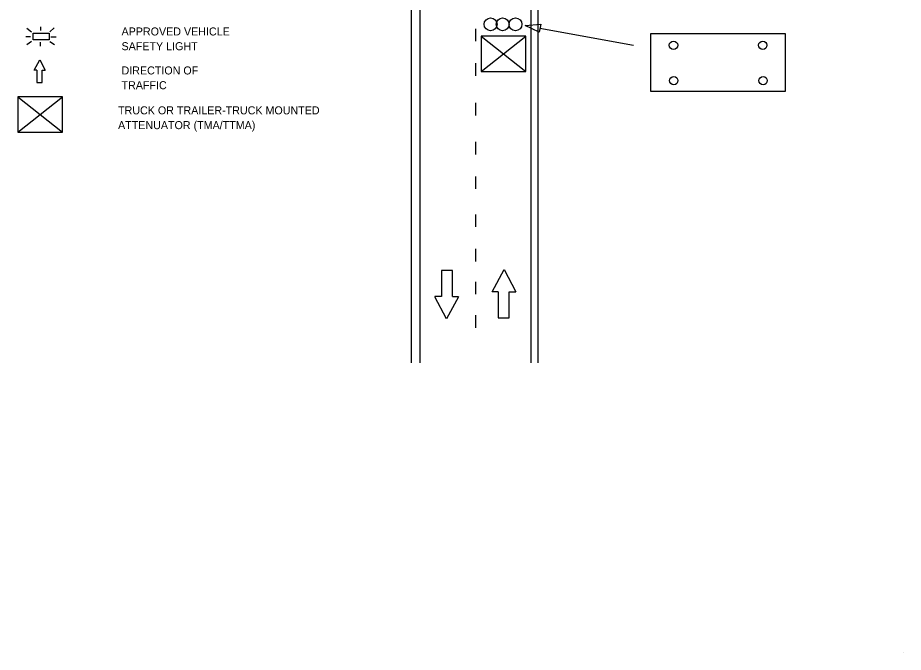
# Model space of a CAD drawing. Extents: x 1531.94 to 1538.58, y 1529.59 to 1539.32.
# Drawn here: x 1531.94 to 1538.58, y 1529.59 to 1534.35 of the extents above; entities that cross this region are included whole.
import ezdxf

# ---------------------------------------------------------------- set-up
doc = ezdxf.new("R2010")
doc.units = 0
for name, color, linetype in [('DETL-DIMS', 7, 'Continuous'), ('DETL-LINE', 7, 'Continuous'), ('DETL-NOTE', 7, 'Continuous'), ('TTLB-TEXT', 7, 'Continuous'), ('USER-BORD', 7, 'Continuous')]:
    doc.layers.add(name, color=color, linetype=linetype)

# ---------------------------------------------------------------- blocks, each defined once
blk = doc.blocks.new('BAR')
at = {"layer": 'USER-BORD'}
for p, q in [((-0.011, 0.0696), (-0.0512, 0.1025)), ((0.0695, 0.1172), (0.0695, 0.0842)), ((0.15, 0.0732), (0.1866, 0.1062)), ((-0.0183, 0.0293), (-0.0585, 0.0293)), ((0.0037, 0.0037), (0.0037, 0.0622)), ((0.0037, 0.0622), (0.1427, 0.0622)), ((0.1427, 0.0037), (0.0037, 0.0037)), ((0.1427, 0.0622), (0.1427, 0.0037)), ((0.1573, 0.0293), (0.2049, 0.0293)), ((-0.011, -0.011), (-0.0512, -0.0403)), ((0.0658, -0.0183), (0.0658, -0.0513)), ((0.15, -0.011), (0.1902, -0.0366))]:
    blk.add_line(p, q, dxfattribs=at)

msp = doc.modelspace()

# ---------------------------------------------------------------- linework, layer by layer
at = {"layer": 'DETL-DIMS'}
msp.add_line((1535.8604, 1534.2712), (1536.5606, 1534.1437), dxfattribs=at)
msp.add_lwpolyline([(1535.7487, 1534.2927), (1535.866, 1534.3021), (1535.8552, 1534.2427)], close=True, dxfattribs=at)
at = {"layer": 'DETL-LINE'}
for p, q in [((1535.7908, 1538.5962), (1535.7908, 1531.7633)), ((1535.8438, 1538.5962), (1535.8438, 1531.7633)), ((1534.8945, 1538.2527), (1534.8945, 1531.7633)), ((1534.9605, 1538.2527), (1534.9605, 1531.7633)), ((1535.3789, 1534.1741), (1535.3789, 1534.2675)), ((1535.754, 1534.2115), (1535.4183, 1534.2115)), ((1535.4183, 1534.2115), (1535.4183, 1533.9471)), ((1535.4183, 1533.9471), (1535.754, 1534.2115)), ((1535.4183, 1534.2115), (1535.754, 1533.9471)), ((1535.754, 1533.9471), (1535.754, 1534.2115)), ((1537.701, 1534.2291), (1536.6891, 1534.2291)), ((1536.6891, 1534.2291), (1536.6891, 1533.7988)), ((1536.8577, 1534.2291), (1536.8577, 1534.2291)), ((1537.0264, 1534.2291), (1537.0264, 1534.2291)), ((1537.195, 1534.2291), (1537.195, 1534.2291)), ((1537.3638, 1534.2291), (1537.3638, 1534.2291)), ((1537.5324, 1534.2291), (1537.5324, 1534.2291)), ((1537.701, 1533.7988), (1537.701, 1534.2291)), ((1532.068, 1533.9567), (1532.1091, 1534.0342)), ((1532.1091, 1534.0342), (1532.1504, 1533.9567)), ((1535.3789, 1533.9158), (1535.3789, 1534.0091)), ((1532.0882, 1533.9563), (1532.0674, 1533.9563)), ((1532.0882, 1533.9563), (1532.0882, 1533.8648)), ((1532.1273, 1533.8648), (1532.1273, 1533.9563)), ((1532.1273, 1533.9563), (1532.1504, 1533.9563)), ((1535.4183, 1533.9471), (1535.754, 1533.9471)), ((1532.0882, 1533.8648), (1532.1273, 1533.8648)), ((1536.6891, 1533.7988), (1537.701, 1533.7988)), ((1531.9443, 1533.7574), (1532.2801, 1533.4931)), ((1531.9443, 1533.4931), (1532.2801, 1533.7574)), ((1531.9443, 1533.7574), (1531.9443, 1533.4931)), ((1532.2801, 1533.7574), (1531.9443, 1533.7574)), ((1532.2801, 1533.4931), (1532.2801, 1533.7574)), ((1535.3789, 1533.6181), (1535.3789, 1533.7115)), ((1531.9443, 1533.4931), (1532.2801, 1533.4931)), ((1535.3789, 1533.3258), (1535.3789, 1533.4192)), ((1535.3789, 1533.0675), (1535.3789, 1533.1608)), ((1535.3789, 1532.7813), (1535.3789, 1532.8747)), ((1535.3789, 1532.5229), (1535.3789, 1532.6163)), ((1535.2052, 1532.4559), (1535.1212, 1532.4559)), ((1535.1212, 1532.4559), (1535.1212, 1532.2596)), ((1535.2052, 1532.2596), (1535.2052, 1532.4559)), ((1535.5027, 1532.2962), (1535.5908, 1532.4625)), ((1535.5908, 1532.4625), (1535.6796, 1532.2962)), ((1535.3789, 1532.2773), (1535.3789, 1532.3708)), ((1535.5458, 1532.2953), (1535.5012, 1532.2953)), ((1535.5458, 1532.2953), (1535.5458, 1532.0989)), ((1535.6299, 1532.0989), (1535.6299, 1532.2953)), ((1535.6299, 1532.2953), (1535.6796, 1532.2953)), ((1535.1212, 1532.2596), (1535.0715, 1532.2596)), ((1535.1602, 1532.0923), (1535.0715, 1532.2585)), ((1535.2484, 1532.2585), (1535.1602, 1532.0923)), ((1535.2052, 1532.2596), (1535.2498, 1532.2596)), ((1535.3789, 1532.0262), (1535.3789, 1532.1196)), ((1535.5458, 1532.0989), (1535.6299, 1532.0989))]:
    msp.add_line(p, q, dxfattribs=at)
for centre, radius in [((1535.4899, 1534.3011), 0.0484), ((1535.5804, 1534.3011), 0.0484), ((1535.6766, 1534.3011), 0.0484), ((1536.8614, 1534.1437), 0.0313), ((1537.5306, 1534.1437), 0.0313), ((1536.8637, 1533.8786), 0.0313), ((1537.5329, 1533.8786), 0.0313)]:
    msp.add_circle(centre, radius, dxfattribs=at)
at = {"layer": 'TTLB-TEXT'}
msp.add_line((1538.5844, 1529.5924), (1538.5844, 1529.5924), dxfattribs=at)

# ---------------------------------------------------------------- block references
at = {"layer": 'DETL-LINE', "xscale": 0.8611764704, "yscale": 0.8611764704}
msp.add_blockref('BAR', (1532.0564, 1534.1822), dxfattribs=at)

# ---------------------------------------------------------------- texts
at = {"layer": 'DETL-NOTE'}
for s, p in [('APPROVED VEHICLE', (1532.7228, 1534.2174)), ('SAFETY LIGHT', (1532.7228, 1534.1067)), ('DIRECTION OF', (1532.7228, 1533.9251)), ('TRAFFIC', (1532.7228, 1533.8144)), ('TRUCK OR TRAILER-TRUCK MOUNTED', (1532.6968, 1533.6259)), ('ATTENUATOR (TMA/TTMA)', (1532.6968, 1533.5151))]:
    msp.add_text(s, height=0.06, dxfattribs=at).set_placement(p)

doc.saveas('drawing.dxf')
